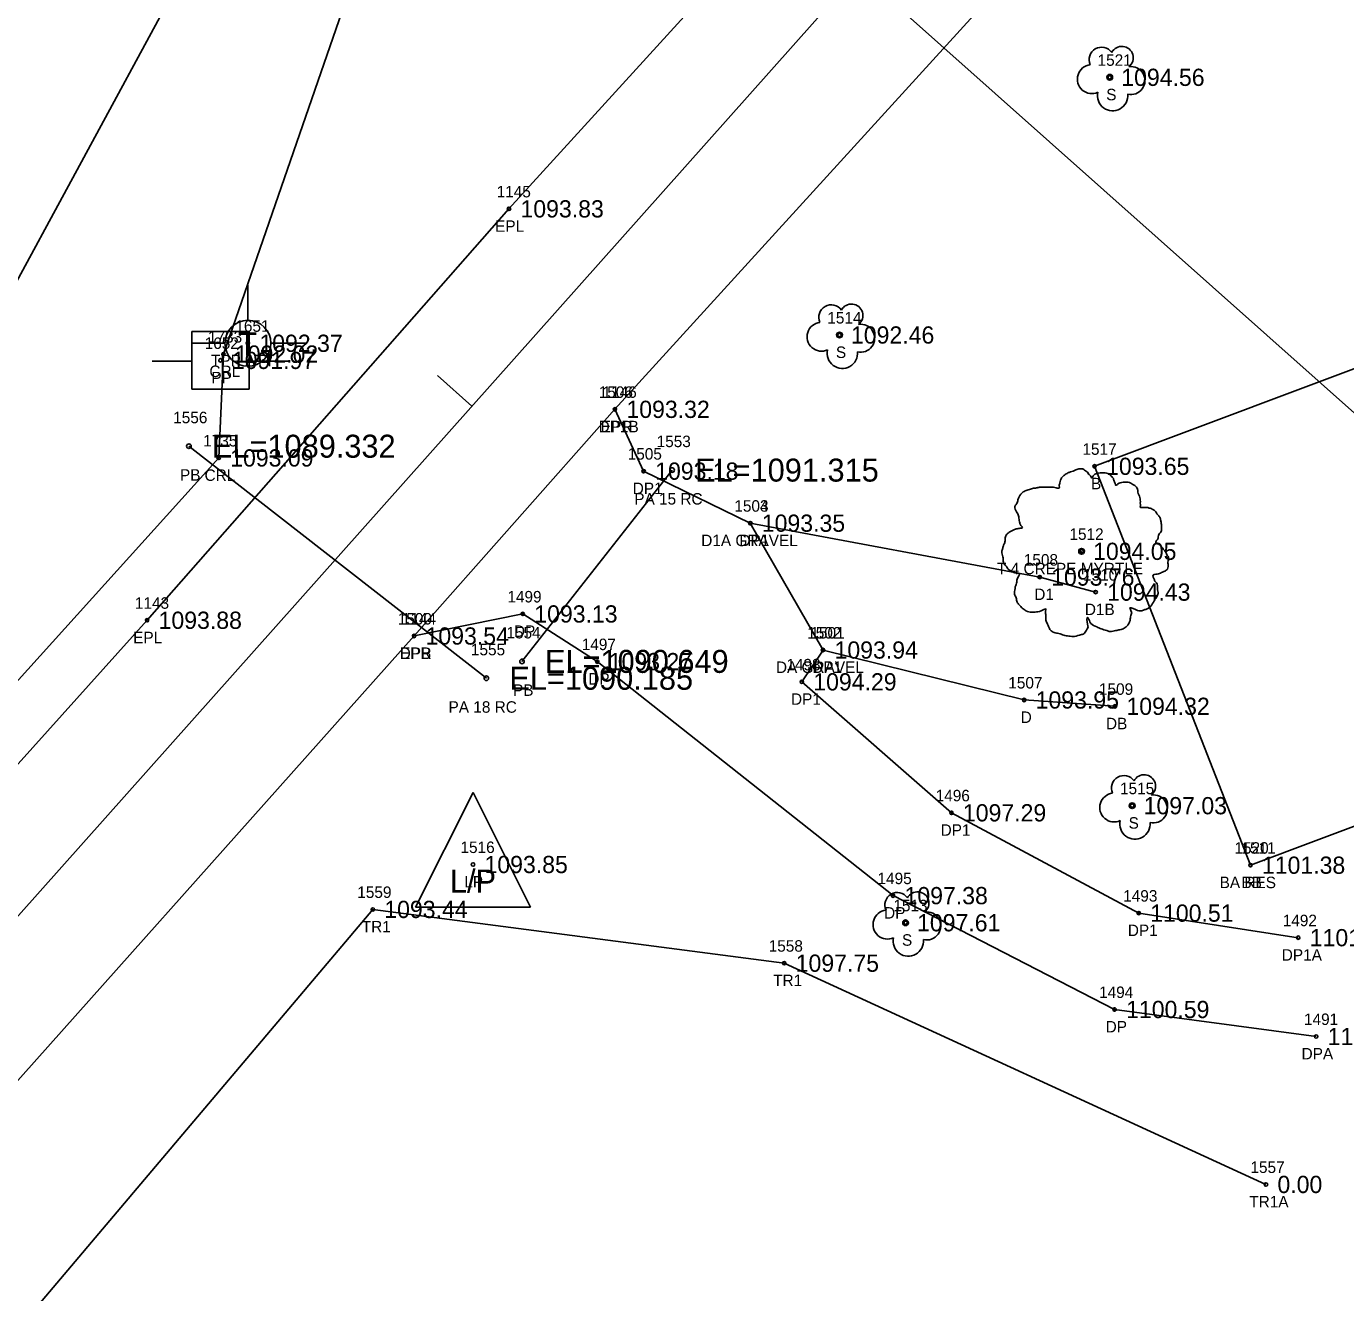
# Model space of a CAD drawing. Extents: x 1539151 to 1541799, y 1198646 to 1201165.
# Drawn here: x 1540728.5 to 1540843.3, y 1200073 to 1200183.3 of the extents above; entities that cross this region are included whole.
import ezdxf

# ---------------------------------------------------------------- set-up
doc = ezdxf.new("R2010")
doc.units = 0
for name, color, linetype in [('RD_EX_Bldg', 7, 'Continuous'), ('RD_EX_Bldg_txCode', 7, 'Continuous'), ('RD_EX_DR_Pipe', 7, 'Continuous'), ('RD_EX_DR_Pipe_txCode', 7, 'Continuous'), ('RD_EX_Driveway', 7, 'Continuous'), ('RD_EX_Driveway_txCode', 7, 'Continuous'), ('RD_EX_H2O', 7, 'Continuous'), ('RD_EX_H2O_txCode', 7, 'Continuous'), ('RD_EX_Road', 7, 'Continuous'), ('RD_EX_Road_txCode', 7, 'Continuous'), ('RD_EX_TX_Bldg_ELEV', 7, 'Continuous'), ('RD_EX_TX_Driveway_ELEV', 7, 'Continuous'), ('RD_EX_TX_H2O_ELEV', 7, 'Continuous'), ('RD_EX_TX_Road_ELEV', 7, 'Continuous'), ('RD_EX_TX_UT_ELEV', 7, 'Continuous'), ('RD_EX_TX_VEG_ELEV', 7, 'Continuous'), ('RD_EX_UT', 7, 'Continuous'), ('RD_EX_UT_txCode', 7, 'Continuous'), ('RD_EX_VEG', 7, 'Continuous'), ('RD_EX_VEG_txCode', 7, 'Continuous'), ('RD_HC_Cl', 7, 'Continuous'), ('RD_HC_Data', 7, 'Continuous'), ('RD_HC_Data_Tic', 7, 'Continuous'), ('RD_HC_Survey_ELEV', 7, 'Continuous'), ('RD_SMD_Locator', 7, 'Continuous'), ('RD_TX_Pipe_ElevEX', 7, 'Continuous')]:
    doc.layers.add(name, color=color, linetype=linetype)

msp = doc.modelspace()

# ---------------------------------------------------------------- linework, layer by layer
at = {"layer": 'RD_EX_Bldg'}
msp.add_lwpolyline([(1540835.02, 1200110.24), (1540821.46, 1200144.96), (1540876.62, 1200165.68), (1540890.17, 1200130.96), (1540835.02, 1200110.24)], dxfattribs=at)
at = {"layer": 'RD_EX_DR_Pipe'}
for p, q in [((1540768.53, 1200126.51), (1540742.65, 1200146.71)), ((1540784.69, 1200144.63), (1540771.63, 1200127.98))]:
    msp.add_line(p, q, dxfattribs=at)
at = {"layer": 'RD_EX_Driveway'}
for points in [[(1540839.18, 1200103.93), (1540825.3, 1200106.07), (1540809, 1200114.8), (1540795.98, 1200126.2), (1540797.83, 1200128.97), (1540791.5, 1200140.01), (1540782.22, 1200144.54), (1540779.72, 1200149.92)], [(1540791.5, 1200140.01), (1540816.68, 1200135.32), (1540821.55, 1200134.01)], [(1540840.74, 1200095.33), (1540823.2, 1200097.68), (1540803.92, 1200107.59), (1540778.18, 1200127.96), (1540771.7, 1200132.11), (1540762.24, 1200130.19)], [(1540797.83, 1200128.97), (1540815.33, 1200124.62), (1540823.23, 1200124.07)]]:
    msp.add_lwpolyline(points, dxfattribs=at)
at = {"layer": 'RD_EX_H2O'}
msp.add_lwpolyline([(1541252.92, 1200441.86), (1541200.84, 1200433.45), (1541140.38, 1200427.39), (1541087.01, 1200428.4), (1541039.74, 1200441.72), (1540997.52, 1200424.93), (1540957.07, 1200418.34), (1540937.15, 1200404.81), (1540902.14, 1200374.36), (1540871.55, 1200334.52), (1540843.47, 1200300.89), (1540819.98, 1200290.97), (1540796.2, 1200252.53), (1540767.65, 1200218.32), (1540745.65, 1200154.73), (1540745.24, 1200145.69), (1540714.12, 1200111.24)], dxfattribs=at)
at = {"layer": 'RD_EX_Road'}
for points in [[(1540705.32, 1200094.04), (1540739.01, 1200131.56), (1540770.5, 1200167.37), (1540805.54, 1200205.85), (1540841.22, 1200241.63), (1540879.37, 1200275.73), (1540919.79, 1200306.26), (1540962.73, 1200334.43), (1541008.04, 1200359.97), (1541051.86, 1200381.29), (1541099.37, 1200400.02), (1541147.99, 1200415.01), (1541197.22, 1200426.76), (1541247.29, 1200435.81)], [(1540718.68, 1200081.33), (1540762.24, 1200130.19), (1540779.72, 1200149.92), (1540818.99, 1200193.09), (1540844.69, 1200219.09), (1540861.59, 1200235.22), (1540891.57, 1200261.37), (1540930.28, 1200290.78), (1540971.82, 1200318.2), (1541015.09, 1200342.79), (1541060.36, 1200364.79), (1541076.53, 1200371.56), (1541099.1, 1200380.09), (1541153.21, 1200396.86), (1541201.21, 1200408.64), (1541249.91, 1200417.32)]]:
    msp.add_lwpolyline(points, dxfattribs=at)
at = {"layer": 'RD_EX_UT'}
for p, q in [((1540747.78, 1200160.74), (1540747.78, 1200157.67)), ((1540747.89, 1200156.68), (1540742.89, 1200156.68)), ((1540742.89, 1200156.68), (1540742.89, 1200151.68)), ((1540747.89, 1200151.68), (1540747.89, 1200156.68)), ((1540742.85, 1200155.69), (1540745.78, 1200155.69)), ((1540749.78, 1200155.69), (1540752.85, 1200155.69)), ((1540739.45, 1200154.12), (1540742.92, 1200154.12)), ((1540747.81, 1200154.12), (1540751.45, 1200154.12)), ((1540742.89, 1200151.68), (1540747.89, 1200151.68)), ((1540762.37, 1200106.58), (1540767.37, 1200116.58)), ((1540767.37, 1200116.58), (1540772.37, 1200106.58)), ((1540762.37, 1200106.58), (1540772.37, 1200106.58))]:
    msp.add_line(p, q, dxfattribs=at)
msp.add_circle((1540747.78, 1200155.67), 2, dxfattribs=at)
at = {"layer": 'RD_EX_VEG'}
msp.add_lwpolyline([(1540836.37, 1200082.45), (1540794.45, 1200101.71), (1540758.65, 1200106.39), (1540697.29, 1200033.83), (1540560.39, 1199886.45), (1540422.51, 1199739.87), (1540382.08, 1199704.72), (1540267.52, 1199610.92), (1540233.68, 1199579.65), (1540209.33, 1199537.96), (1540187.75, 1199496.51), (1540221.64, 1199381.22)], dxfattribs=at)
for centre, radius in [((1540822.78, 1200178.82), 0.25), ((1540799.26, 1200156.39), 0.25), ((1540820.33, 1200137.56), 0.25), ((1540820.32, 1200137.54), 0.0001), ((1540824.73, 1200115.42), 0.25), ((1540805.01, 1200105.23), 0.25)]:
    msp.add_circle(centre, radius, dxfattribs=at)
for centre, radius, start, end in [((1540822.06, 1200180.36), 1.08, 34.9763, 204.756), ((1540823.83, 1200180.52), 0.995, 308.7626, 152.0467), ((1540821.22, 1200178.66), 1.26, 96.4518, 294.734), ((1540824.62, 1200178.54), 1.22, 256.5667, 98.1046), ((1540823.03, 1200177.22), 1.32, 166.8827, 5.7589), ((1540798.54, 1200157.94), 1.08, 34.9763, 204.756), ((1540800.3, 1200158.09), 0.995, 308.7626, 152.0467), ((1540797.7, 1200156.24), 1.26, 96.4518, 294.734), ((1540801.1, 1200156.11), 1.22, 256.5667, 98.1046), ((1540799.51, 1200154.8), 1.32, 166.8827, 5.7589), ((1540825.77, 1200117.12), 0.995, 308.7626, 152.0467), ((1540824.01, 1200116.96), 1.08, 34.9763, 204.756), ((1540823.17, 1200115.26), 1.26, 96.4518, 294.734), ((1540826.57, 1200115.14), 1.22, 256.5667, 98.1046), ((1540824.97, 1200113.82), 1.32, 166.8827, 5.7589), ((1540804.29, 1200106.78), 1.08, 34.9763, 204.756), ((1540806.05, 1200106.93), 0.995, 308.7626, 152.0467), ((1540803.44, 1200105.07), 1.26, 96.4518, 294.734), ((1540806.85, 1200104.95), 1.22, 256.5667, 98.1046), ((1540805.25, 1200103.63), 1.32, 166.8827, 5.7589)]:
    msp.add_arc(centre, radius, start, end, dxfattribs=at)
for points in [[(1540820.46, 1200144.73), (1540820.16, 1200144.75), (1540819.84, 1200144.65), (1540819.59, 1200144.55), (1540819.37, 1200144.48), (1540819.14, 1200144.38), (1540818.84, 1200144.2), (1540818.62, 1200144), (1540818.49, 1200143.75), (1540818.44, 1200143.53), (1540818.39, 1200143.25), (1540818.39, 1200143.08), (1540818.27, 1200143.05), (1540818.12, 1200143.08), (1540817.87, 1200143.15), (1540817.62, 1200143.15), (1540817.37, 1200143.15), (1540817.02, 1200143.13), (1540816.67, 1200143.13), (1540816.39, 1200143.08), (1540816.07, 1200143.03), (1540815.69, 1200142.9), (1540815.34, 1200142.78), (1540815.04, 1200142.53), (1540814.79, 1200142.05), (1540814.67, 1200141.7), (1540814.52, 1200141.45), (1540814.67, 1200141), (1540814.84, 1200140.65), (1540814.87, 1200140.45), (1540814.94, 1200140.03), (1540815.04, 1200139.8), (1540815.17, 1200139.6), (1540815.09, 1200139.58), (1540814.72, 1200139.53), (1540814.42, 1200139.43), (1540813.99, 1200139.2), (1540813.77, 1200138.98), (1540813.67, 1200138.65), (1540813.64, 1200138.3), (1540813.54, 1200138.1), (1540813.47, 1200137.83), (1540813.44, 1200137.75), (1540813.39, 1200137.43), (1540813.49, 1200136.98), (1540813.52, 1200136.63), (1540813.64, 1200136.4), (1540813.79, 1200136.23), (1540813.97, 1200135.98), (1540814.37, 1200135.76), (1540814.69, 1200135.66), (1540814.89, 1200135.63), (1540814.72, 1200135.13), (1540814.67, 1200134.78), (1540814.54, 1200134.38), (1540814.54, 1200134.31), (1540814.49, 1200133.83), (1540814.64, 1200133.51), (1540814.72, 1200133.13), (1540814.89, 1200132.91), (1540815.17, 1200132.61), (1540815.49, 1200132.38), (1540815.99, 1200132.26), (1540816.39, 1200132.28), (1540816.97, 1200132.46), (1540817.22, 1200132.53), (1540817.19, 1200132.36), (1540817.22, 1200131.98), (1540817.22, 1200131.56), (1540817.37, 1200131.23), (1540817.47, 1200130.96), (1540817.62, 1200130.71), (1540817.94, 1200130.48), (1540818.34, 1200130.41), (1540818.77, 1200130.26), (1540819.22, 1200130.18), (1540819.72, 1200130.16), (1540820.31, 1200130.31), (1540820.59, 1200130.43), (1540820.69, 1200130.61), (1540820.89, 1200130.98), (1540820.84, 1200131.21), (1540820.86, 1200131.81), (1540820.96, 1200131.63), (1540821.14, 1200131.28), (1540821.64, 1200130.98), (1540822.04, 1200130.81), (1540822.51, 1200130.66), (1540822.81, 1200130.58), (1540823.29, 1200130.66), (1540823.66, 1200130.73), (1540824.04, 1200130.86), (1540824.34, 1200131.13), (1540824.51, 1200131.41), (1540824.56, 1200131.68), (1540824.64, 1200132.06), (1540824.69, 1200132.23)], [(1540824.69, 1200132.23), (1540824.61, 1200132.41), (1540824.56, 1200132.66), (1540824.64, 1200132.63), (1540824.81, 1200132.58), (1540825.09, 1200132.46), (1540825.31, 1200132.38), (1540825.64, 1200132.41), (1540825.91, 1200132.51), (1540826.36, 1200132.78), (1540826.64, 1200133.26), (1540826.91, 1200133.66), (1540826.99, 1200133.98), (1540826.94, 1200134.21), (1540826.91, 1200134.71), (1540826.71, 1200134.96), (1540826.66, 1200135.08), (1540826.56, 1200135.48), (1540826.64, 1200135.53), (1540826.91, 1200135.58), (1540827.29, 1200135.71), (1540827.56, 1200135.83), (1540827.79, 1200136.01), (1540827.86, 1200136.23), (1540827.84, 1200136.63), (1540827.89, 1200137.03), (1540827.81, 1200137.18), (1540827.71, 1200137.33), (1540827.64, 1200137.53), (1540827.49, 1200137.68), (1540827.39, 1200137.83), (1540827.29, 1200137.93), (1540827.16, 1200138.08), (1540826.99, 1200138.2), (1540826.84, 1200138.25), (1540826.79, 1200138.4), (1540826.94, 1200138.6), (1540826.99, 1200138.7), (1540827.01, 1200138.93), (1540827.24, 1200139.28), (1540827.29, 1200139.68), (1540827.24, 1200140.1), (1540827.19, 1200140.38), (1540827.04, 1200140.65), (1540826.84, 1200140.9), (1540826.71, 1200141.08), (1540826.54, 1200141.2), (1540826.21, 1200141.33), (1540825.96, 1200141.38), (1540825.61, 1200141.38), (1540825.41, 1200141.43), (1540825.44, 1200141.48), (1540825.44, 1200141.63), (1540825.44, 1200141.9), (1540825.36, 1200142.35), (1540825.21, 1200142.85), (1540825.21, 1200142.88), (1540825.11, 1200143.13), (1540824.89, 1200143.33), (1540824.71, 1200143.43), (1540824.51, 1200143.55), (1540824.26, 1200143.58), (1540823.96, 1200143.58), (1540823.69, 1200143.53), (1540823.49, 1200143.43), (1540823.31, 1200143.3), (1540823.24, 1200143.45), (1540823.14, 1200143.75), (1540823.09, 1200143.9), (1540822.94, 1200144.08), (1540822.71, 1200144.28), (1540822.26, 1200144.4), (1540821.64, 1200144.33), (1540821.34, 1200144.13), (1540821.19, 1200143.95), (1540821.14, 1200144.08), (1540820.94, 1200144.28), (1540820.84, 1200144.45), (1540820.66, 1200144.58), (1540820.51, 1200144.68), (1540820.41, 1200144.73)]]:
    msp.add_spline(points, degree=3, dxfattribs=at)
at = {"layer": 'RD_HC_Cl'}
for p, q in [((1540815.59, 1200323.52), (1540714.91, 1200137.52)), ((1540452.58, 1199796.65), (1540800.92, 1200188))]:
    msp.add_line(p, q, dxfattribs=at)
at = {"layer": 'RD_HC_Data'}
msp.add_line((1540800.92, 1200188), (1540888.08, 1200110.41), dxfattribs=at)
at = {"layer": 'RD_HC_Data_Tic'}
msp.add_line((1540767.28, 1200150.2), (1540764.29, 1200152.86), dxfattribs=at)
at = {"layer": 'RD_SMD_Locator'}
for centre, radius in [((1540822.78, 1200178.82), 0.15), ((1540770.5, 1200167.37), 0.15), ((1540799.26, 1200156.39), 0.15), ((1540745.65, 1200154.73), 0.15), ((1540747.78, 1200155.67), 0.15), ((1540745.39, 1200154.18), 0.15), ((1540779.72, 1200149.92), 0.15), ((1540779.72, 1200149.92), 0.15), ((1540742.65, 1200146.71), 0.2), ((1540745.24, 1200145.69), 0.15), ((1540782.22, 1200144.54), 0.15), ((1540784.69, 1200144.63), 0.2), ((1540821.46, 1200144.96), 0.15), ((1540791.5, 1200140.01), 0.15), ((1540791.5, 1200140.01), 0.15), ((1540820.33, 1200137.56), 0.15), ((1540816.68, 1200135.32), 0.15), ((1540821.55, 1200134.01), 0.15), ((1540771.7, 1200132.11), 0.15), ((1540739.01, 1200131.56), 0.15), ((1540762.24, 1200130.19), 0.15), ((1540762.24, 1200130.19), 0.15), ((1540797.83, 1200128.97), 0.15), ((1540797.83, 1200128.97), 0.15), ((1540771.63, 1200127.98), 0.2), ((1540778.18, 1200127.96), 0.15), ((1540768.53, 1200126.51), 0.2), ((1540795.98, 1200126.2), 0.15), ((1540815.33, 1200124.62), 0.15), ((1540823.23, 1200124.07), 0.15), ((1540809, 1200114.8), 0.15), ((1540824.73, 1200115.42), 0.15), ((1540767.37, 1200110.3), 0.15), ((1540835.02, 1200110.24), 0.15), ((1540835.02, 1200110.24), 0.15), ((1540803.92, 1200107.59), 0.15), ((1540758.65, 1200106.39), 0.15), ((1540825.3, 1200106.07), 0.15), ((1540805.01, 1200105.23), 0.15), ((1540839.18, 1200103.93), 0.15), ((1540794.45, 1200101.71), 0.15), ((1540823.2, 1200097.68), 0.15), ((1540840.74, 1200095.33), 0.15), ((1540836.37, 1200082.45), 0.15)]:
    msp.add_circle(centre, radius, dxfattribs=at)

# ---------------------------------------------------------------- texts
at = {"layer": 'RD_EX_Bldg_txCode'}
for s, p in [('1517', (1540820.4, 1200145.96)), ('B', (1540821.15, 1200142.96)), ('1520', (1540833.63, 1200111.24)), ('1511', (1540834.24, 1200111.24)), ('BA RES', (1540832.34, 1200108.24)), ('BB', (1540834.24, 1200108.24))]:
    msp.add_text(s, height=1, dxfattribs=at).set_placement(p)
at = {"layer": 'RD_EX_DR_Pipe_txCode'}
for s, p in [('1556', (1540741.28, 1200148.71)), ('1553', (1540783.35, 1200146.63)), ('PB', (1540741.87, 1200143.71)), ('PA 15 RC', (1540781.4, 1200141.63)), ('1554', (1540770.28, 1200129.98)), ('1555', (1540767.19, 1200128.51)), ('PB', (1540770.85, 1200124.98)), ('PA 18 RC', (1540765.24, 1200123.51))]:
    msp.add_text(s, height=1, dxfattribs=at).set_placement(p)
at = {"layer": 'RD_EX_Driveway_txCode'}
for s, p in [('1506', (1540778.31, 1200150.92)), ('DP1B', (1540778.3, 1200147.92)), ('1505', (1540780.83, 1200145.54)), ('DP1', (1540781.27, 1200142.54)), ('1503', (1540790.11, 1200141.01)), ('1504', (1540790.11, 1200141.01)), ('D1A GRAVEL', (1540787.23, 1200138.01)), ('DP1', (1540790.55, 1200138.01)), ('1508', (1540815.3, 1200136.32)), ('1510', (1540820.45, 1200135.01)), ('D1', (1540816.21, 1200133.32)), ('1499', (1540770.36, 1200133.11)), ('D1B', (1540820.61, 1200132.01)), ('1500', (1540760.82, 1200131.19)), ('DP', (1540770.93, 1200130.11)), ('1502', (1540796.45, 1200129.97)), ('1501', (1540796.73, 1200129.97)), ('1497', (1540776.83, 1200128.96)), ('DPB', (1540760.99, 1200128.19)), ('DA GRAVEL', (1540793.73, 1200126.97)), ('1498', (1540794.64, 1200127.2)), ('DP1', (1540796.89, 1200126.97)), ('DP', (1540777.4, 1200125.96)), ('1507', (1540813.95, 1200125.62)), ('DP1', (1540795.04, 1200124.2)), ('1509', (1540821.84, 1200125.07)), ('D', (1540815.03, 1200122.62)), ('DB', (1540822.45, 1200122.07)), ('1496', (1540807.63, 1200115.8)), ('DP1', (1540808.06, 1200112.8)), ('1495', (1540802.57, 1200108.59)), ('1493', (1540823.95, 1200107.07)), ('DP', (1540803.14, 1200105.59)), ('1492', (1540837.83, 1200104.93)), ('DP1', (1540824.35, 1200104.07)), ('DP1A', (1540837.75, 1200101.93)), ('1494', (1540821.85, 1200098.68)), ('DP', (1540822.42, 1200095.68)), ('1491', (1540839.68, 1200096.33)), ('DPA', (1540839.47, 1200093.33))]:
    msp.add_text(s, height=1, dxfattribs=at).set_placement(p)
at = {"layer": 'RD_EX_H2O_txCode'}
for s, p in [('1733', (1540744.31, 1200155.73)), ('CRL', (1540744.43, 1200152.73)), ('1735', (1540743.89, 1200146.69)), ('CRL', (1540744.01, 1200143.69))]:
    msp.add_text(s, height=1, dxfattribs=at).set_placement(p)
at = {"layer": 'RD_EX_Road_txCode'}
for s, p in [('1145', (1540769.43, 1200168.37)), ('EPL', (1540769.29, 1200165.37)), ('1146', (1540778.64, 1200150.92)), ('EPR', (1540778.49, 1200147.92)), ('1143', (1540737.95, 1200132.56)), ('1144', (1540761.18, 1200131.19)), ('EPL', (1540737.8, 1200129.56)), ('EPR', (1540761.01, 1200128.19))]:
    msp.add_text(s, height=1, dxfattribs=at).set_placement(p)
at = {"layer": 'RD_EX_TX_Bldg_ELEV'}
for s, p in [('1093.65', (1540822.46, 1200144.21)), ('1101.38', (1540836.02, 1200109.49)), ('1101.38', (1540836.02, 1200109.49))]:
    msp.add_text(s, height=1.5, dxfattribs=at).set_placement(p)
at = {"layer": 'RD_EX_TX_Driveway_ELEV'}
for s, p in [('1093.32', (1540780.72, 1200149.17)), ('1093.18', (1540783.22, 1200143.79)), ('1093.35', (1540792.5, 1200139.26)), ('1093.35', (1540792.5, 1200139.26)), ('1093.76', (1540817.68, 1200134.57)), ('1094.43', (1540822.55, 1200133.26)), ('1093.13', (1540772.7, 1200131.36)), ('1093.54', (1540763.24, 1200129.44)), ('1093.94', (1540798.83, 1200128.22)), ('1093.94', (1540798.83, 1200128.22)), ('1093.27', (1540779.18, 1200127.21)), ('1094.29', (1540796.98, 1200125.45)), ('1093.95', (1540816.33, 1200123.87)), ('1094.32', (1540824.23, 1200123.32)), ('1097.29', (1540810, 1200114.05)), ('1097.38', (1540804.92, 1200106.84)), ('1100.51', (1540826.3, 1200105.32)), ('1101.75', (1540840.18, 1200103.18)), ('1100.59', (1540824.2, 1200096.93)), ('1101.87', (1540841.74, 1200094.58))]:
    msp.add_text(s, height=1.5, dxfattribs=at).set_placement(p)
at = {"layer": 'RD_EX_TX_H2O_ELEV'}
for s, p in [('1092.02', (1540746.65, 1200153.98)), ('1093.09', (1540746.24, 1200144.94))]:
    msp.add_text(s, height=1.5, dxfattribs=at).set_placement(p)
at = {"layer": 'RD_EX_TX_Road_ELEV'}
for s, p in [('1093.83', (1540771.5, 1200166.62)), ('1093.32', (1540780.72, 1200149.17)), ('1093.88', (1540740.01, 1200130.81)), ('1093.54', (1540763.24, 1200129.44))]:
    msp.add_text(s, height=1.5, dxfattribs=at).set_placement(p)
at = {"layer": 'RD_EX_TX_UT_ELEV'}
for s, p in [('1092.37', (1540748.78, 1200154.92)), ('1093.85', (1540768.37, 1200109.55))]:
    msp.add_text(s, height=1.5, dxfattribs=at).set_placement(p)
at = {"layer": 'RD_EX_TX_VEG_ELEV'}
for s, p in [('1094.56', (1540823.78, 1200178.07)), ('1092.46', (1540800.26, 1200155.64)), ('1094.05', (1540821.33, 1200136.81)), ('1097.03', (1540825.73, 1200114.67)), ('1093.44', (1540759.65, 1200105.64)), ('1097.61', (1540806.01, 1200104.48)), ('1097.75', (1540795.45, 1200100.96)), ('0.00', (1540837.37, 1200081.7))]:
    msp.add_text(s, height=1.5, dxfattribs=at).set_placement(p)
at = {"layer": 'RD_EX_UT'}
for s, p in [('T', (1540746.93, 1200154.62)), ('L/P', (1540765.36, 1200107.86))]:
    msp.add_text(s, height=2, dxfattribs=at).set_placement(p)
at = {"layer": 'RD_EX_UT_txCode'}
for s, p in [('1651', (1540746.69, 1200156.67)), ('1652', (1540744.02, 1200155.18)), ('TPP ATT', (1540744.57, 1200153.67)), ('PP', (1540744.61, 1200152.18)), ('1516', (1540766.28, 1200111.3)), ('LP', (1540766.61, 1200108.3))]:
    msp.add_text(s, height=1, dxfattribs=at).set_placement(p)
at = {"layer": 'RD_EX_VEG_txCode'}
for s, p in [('1521', (1540821.72, 1200179.82)), ('S', (1540822.47, 1200176.82)), ('1514', (1540798.2, 1200157.39)), ('S', (1540798.95, 1200154.39)), ('1512', (1540819.27, 1200138.56)), ('T 4 CREPE MYRTLE', (1540812.97, 1200135.56)), ('1515', (1540823.67, 1200116.42)), ('S', (1540824.42, 1200113.42)), ('1559', (1540757.3, 1200107.39)), ('1513', (1540803.95, 1200106.23)), ('TR1', (1540757.69, 1200104.39)), ('1558', (1540793.1, 1200102.71)), ('S', (1540804.7, 1200103.23)), ('TR1', (1540793.49, 1200099.71)), ('1557', (1540835.02, 1200083.45)), ('TR1A', (1540834.92, 1200080.45))]:
    msp.add_text(s, height=1, dxfattribs=at).set_placement(p)
at = {"layer": 'RD_HC_Survey_ELEV'}
msp.add_text('1091.97', height=1.5, dxfattribs=at).set_placement((1540746.39, 1200153.43))
at = {"layer": 'RD_TX_Pipe_ElevEX'}
for s, p in [('EL=1089.332', (1540744.65, 1200145.71)), ('EL=1091.315', (1540786.69, 1200143.63)), ('EL=1090.649', (1540773.63, 1200126.98)), ('EL=1090.185', (1540770.53, 1200125.51))]:
    msp.add_text(s, height=2, dxfattribs=at).set_placement(p)

doc.saveas('drawing.dxf')
